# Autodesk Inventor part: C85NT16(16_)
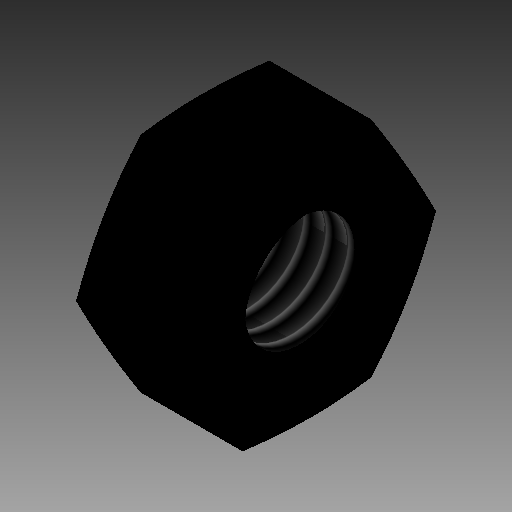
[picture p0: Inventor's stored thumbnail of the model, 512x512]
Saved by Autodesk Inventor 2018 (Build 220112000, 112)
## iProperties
Category: PARTsolutions
Company: SMC
Part Number: C85NT16(16_)
Material: Generic
Catalog Web Link: www.cadenas.de
Description: C85/CD85 ROD_NUT-ISO Standard Air Cylinder:Standard Type Double Acting Single Rod
Vendor: SMC
Document SubType Name: Modeling
Designer: partserver
Manufacturer: SMC
Mass: 0.332201 g
Surface Area: 3.72276 cm^2
Volume: 0.332201 cm^3
Density: 1 g/cm^3
Appearance: PSOLRGB-0-0-0
PSOL_IDENT_0: {$CADENAS_DATA\23d-libs\smc_jp\actuator\standard_air_cylinder\c85\c85\parts\c85_rod_nut.prj},173 {VT
PSOL_IDENT_1: YP=3D},{NB=C85NT16(16_)},{LINA=C85NT16},{NN=C85/CD85 ROD_NUT},{DATE=09.12.2020 03:32:11},{GEOMDATE=2
PSOL_IDENT_2: 6.04.2020 05:22:00},{VERSION=},{LINEID=40},{WBVAR=OMSC},{WBNUMERIC=}  {NB=C85NT16(16_)},{LINA=C85NT1
PSOL_IDENT_3: 6},{KT=DUMMY},{MODEL=C85NT16},{BORE=16},{OMSC=},{KK=M6x1},{KKD=6.000},{KKJ=1.000},{SW=10},{H=5.0}
NB: C85NT16(16_)
NN: C85/CD85 ROD_NUT
NT: ISO Standard Air Cylinder:Standard Type Double Acting Single Rod
NBSYN: $MODEL.($BORE._$OMSC.)
LINA: C85NT16
CATALOG: SMC (JP
BORE: 16
OMSC: (-) Without order
KK: M6x1
KKD: 6
KKJ: 1
SW: 10
H: 5
SUPPLIER: SMC
ARTICLENO: C85NT16(16_)
BOMINFO: C85NT16
CREATOR: CADENAS GmbH
Title: C85NT16
Author: Cadenas PARTsolutions
Comments: ISO Standard Air Cylinder:Standard Type Double Acting Single Rod
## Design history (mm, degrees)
sketch "Sketch_1"
  geometry: L1 (5, 0)-(0, 0); L2 (0, 5)-(0, 3); L3 (0, 3)-(0.542, 2.458); L4 (0.542, 2.458)-(4.458, 2.458); L5 (4.458, 2.458)-(5, 3); L6 (5, 3)-(5, 5); L7 (5, 5)-(2.5, 14.33); L8 (2.5, 14.33)-(0, 5)
  constraints: 16 end point
revolve "Revolution1" sketch "Sketch_1" stored, may be unused: angle "d0" = 360 deg
thread "Thread1" dims "d1" = 3.917, "d2" = 0
sketch "Sketch_2"
  geometry: L1 (-2.887, 5)-(-5.774, 0); L2 (-5.774, 0)-(-2.887, -5); L3 (-2.887, -5)-(2.887, -5); L4 (2.887, -5)-(5.774, 0); L5 (5.774, 0)-(2.887, 5); L6 (2.887, 5)-(-2.887, 5); C1 r 15 at (0, 0); 1 further point
  constraints: 12 end point, 1 centre point
extrude "Extrusion1" cut sketch "Sketch_2" distance "d3" = 5; taper "d4" = 0 deg
node "RODNUT_ROD_XY"
node "RODNUT_ROD_YZ"
node "RODNUT_ROD_ZX"
node "RODNUT_ROD_X"
node "RODNUT_ROD_Y"
node "RODNUT_ROD_Z"
node "RODNUT_ROD_Center"
body "Solid1"
